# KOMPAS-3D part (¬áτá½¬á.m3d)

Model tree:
1. Эскиз:1
2. Операция выдавливания:1
     Расстояние 1 = 2
3. Скругление:1
     Радиус = 1
4. Скругление:2
     Радиус = 0.2

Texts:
  Сплав АЛ8  ГОСТ 1583-93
